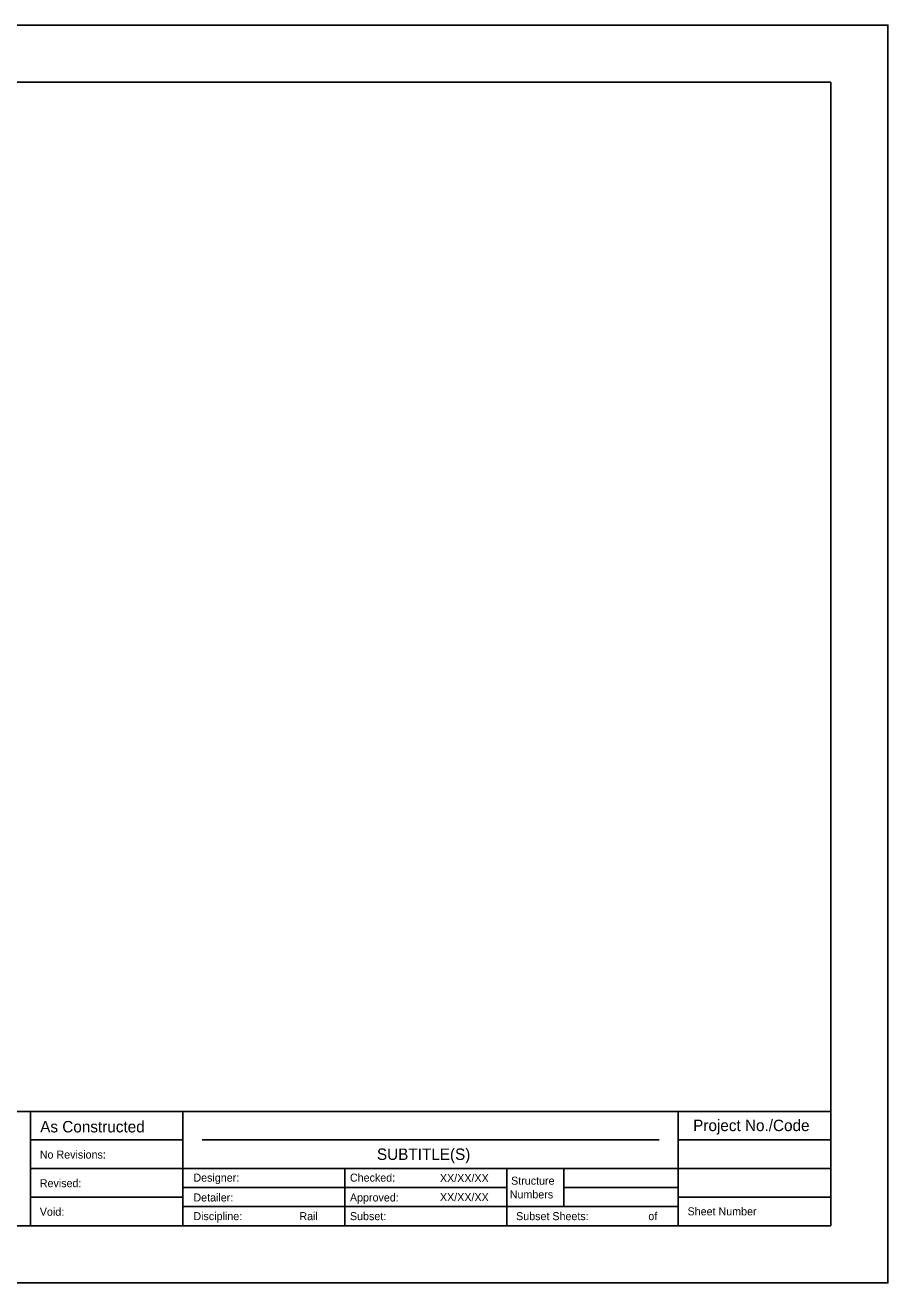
# Model space of a CAD drawing. Extents: x 0 to 1.42, y 0 to 0.92.
# Drawn here: x 0.788 to 1.417, y 0 to 0.917 of the extents above; entities that cross this region are included whole.
import ezdxf

# ---------------------------------------------------------------- set-up
doc = ezdxf.new("R2010")
doc.units = 0
for name, color, linetype in [('SHEET_Grid-Major', 7, 'Continuous'), ('SHEET_Lines', 7, 'Continuous'), ('SHEET_Plot Boundary', 7, 'Continuous'), ('SHEET_Text-Border Info', 7, 'Continuous'), ('SHEET_Text-Titles', 7, 'Continuous')]:
    doc.layers.add(name, color=color, linetype=linetype)

msp = doc.modelspace()

# ---------------------------------------------------------------- linework, layer by layer
at = {"layer": 'SHEET_Grid-Major'}
msp.add_line((0.91681, 0.10417), (1.24985, 0.10417), dxfattribs=at)
at = {"layer": 'SHEET_Lines'}
for p, q in [((0.08333, 0.875), (1.375, 0.875)), ((1.375, 0.875), (1.375, 0.04167)), ((1.375, 0.125), (0.08333, 0.125)), ((0.79167, 0.04167), (0.79167, 0.125)), ((0.90278, 0.125), (0.90278, 0.04167)), ((1.26389, 0.125), (1.26389, 0.04167)), ((0.79167, 0.10417), (0.90278, 0.10417)), ((1.26389, 0.10417), (1.375, 0.10417)), ((0.79167, 0.08333), (1.375, 0.08333)), ((1.02083, 0.08333), (1.02083, 0.04167)), ((1.13889, 0.08333), (1.13889, 0.04167)), ((1.18055, 0.08333), (1.18055, 0.05556)), ((0.90278, 0.06944), (1.13889, 0.06944)), ((1.26389, 0.06944), (1.18055, 0.06944)), ((0.79167, 0.0625), (0.90278, 0.0625)), ((0.90278, 0.05556), (1.26389, 0.05556)), ((1.26389, 0.0625), (1.375, 0.0625)), ((0.08333, 0.04167), (1.375, 0.04167))]:
    msp.add_line(p, q, dxfattribs=at)
at = {"layer": 'SHEET_Plot Boundary'}
msp.add_lwpolyline([(0, 0.91666), (1.41666, 0.91666), (1.41666, 0), (0, 0)], close=True, dxfattribs=at)

# ---------------------------------------------------------------- texts
at = {"layer": 'SHEET_Text-Border Info'}
for s, height, p in [('No Revisions:', 0.0058333, (0.79844, 0.09056)), ('Revised:', 0.005833, (0.79844, 0.06972)), ('Designer:', 0.005833, (0.91042, 0.07377)), ('Checked:', 0.005833, (1.02453, 0.07377)), ('XX/XX/XX', 0.005833, (1.09014, 0.07347)), ('Structure', 0.005833, (1.14202, 0.07153)), ('Detailer:', 0.005833, (0.91042, 0.05931)), ('Approved:', 0.005833, (1.02453, 0.05931)), ('XX/XX/XX', 0.005833, (1.09014, 0.05958)), ('Numbers', 0.005833, (1.14103, 0.06153)), ('Void:', 0.005833, (0.79844, 0.04889)), ('Sheet Number', 0.0058333, (1.27066, 0.04917)), ('Discipline:', 0.0058333, (0.91042, 0.04569)), ('    Rail', 0.005833, (0.97899, 0.04569)), ('Subset:', 0.005833, (1.02453, 0.04569)), ('Subset Sheets:', 0.0058333, (1.14566, 0.04569)), (' of ', 0.005833, (1.2399, 0.04569))]:
    msp.add_text(s, height=height, dxfattribs=at).set_placement(p)
at = {"layer": 'SHEET_Text-Titles'}
for s, p in [('Project No./Code', (1.27473, 0.11059)), ('As Constructed', (0.79872, 0.10964)), ('SUBTITLE(S)', (1.0442, 0.08958))]:
    msp.add_text(s, height=0.0083333, dxfattribs=at).set_placement(p)

doc.saveas('drawing.dxf')
